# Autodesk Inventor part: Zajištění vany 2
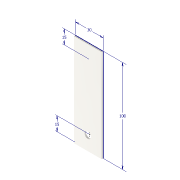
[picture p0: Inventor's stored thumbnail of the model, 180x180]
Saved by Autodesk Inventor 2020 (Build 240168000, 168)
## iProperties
Created: 2025-03
Part Number: Zajištění vany 2
Material: Ocel
Document SubType Name: Modeling
Designer: doma
Density: 7.85 g/cm^3
Appearance: Ocel
Author: doma
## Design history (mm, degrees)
sketch "Náčrt1"
  geometry: L1 (-15, -50)-(15, -50); L2 (15, -50)-(15, 50); L3 (15, 50)-(-15, 50); L4 (-15, 50)-(-15, -50); L5 (-15, -50)-(15, 50); L6 (15, -50)-(-15, 50); L7 (0, 50)-(0, 35); 2 further points
  constraints: 14 end point, 3 midpoint, 2 parallel, 1 horizontal, 1 perpendicular, 1 vertical
  dimensions: "d3" = 30 distance of L3.end L2.end; "d4" = 100 distance of L2.end L1.end; "d14" = 15 distance of L7.start L7.end; "d15" = 15 distance from line of L1 point (0, -35)
extrude "Vysunutí1" new body sketch "Náčrt1" distance "d5" = 1.6; taper "d6" = 0 deg
hole "Díra1" sketch "Náčrt1" diameter "d7" = 7; stored, may be unused: countersink angle "d11" = 90 deg, drill point angle "d13" = 118 deg; dims "d8" = 6, "d9" = 4, "d10" = 2, "d12" = 8
node "Těleso1"
